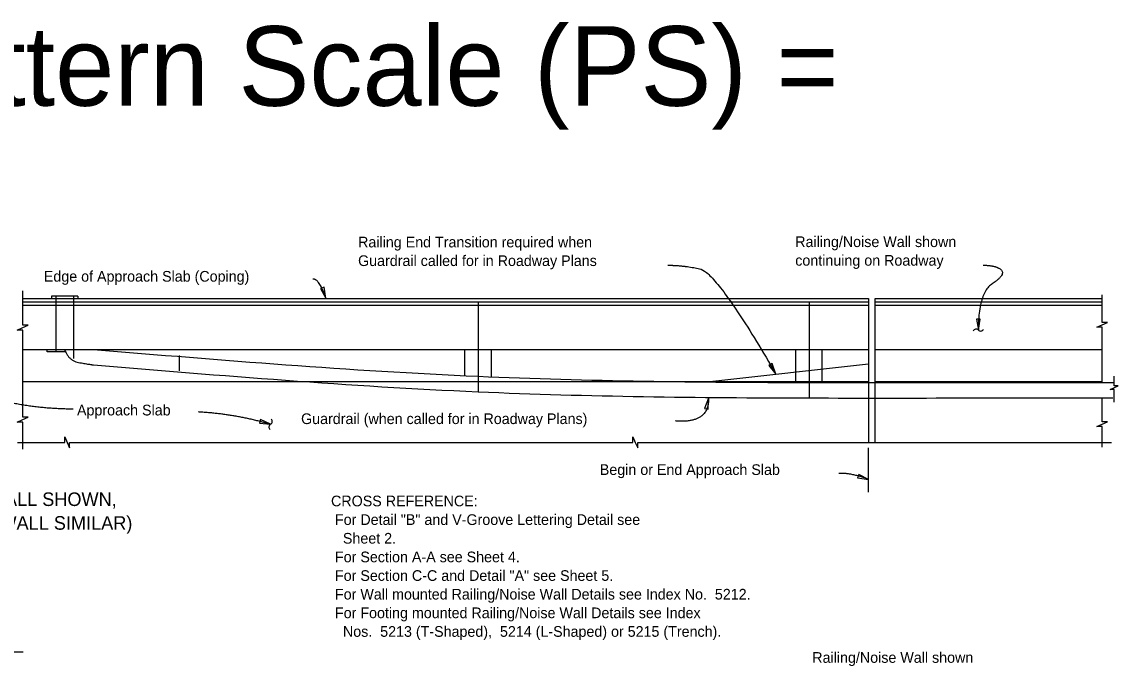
# Model space of a CAD drawing. Extents: x 120631.6 to 120706.2, y 120663.5 to 120716.4.
# Drawn here: x 120654.13 to 120674.84, y 120703.76 to 120715.93 of the extents above; entities that cross this region are included whole.
import ezdxf

# ---------------------------------------------------------------- set-up
doc = ezdxf.new("R2010")
doc.units = 0
for name, color, linetype in [('CL_Minor', 7, 'Continuous'), ('Dimension', 7, 'Continuous'), ('SteelMisc_h', 7, 'Continuous'), ('TextStructures', 7, 'Continuous'), ('TrafBarrierConc', 7, 'Continuous')]:
    doc.layers.add(name, color=color, linetype=linetype)

msp = doc.modelspace()

# ---------------------------------------------------------------- linework, layer by layer
at = {"layer": 'CL_Minor'}
for p, q in [((120654.773, 120710.751), (120654.773, 120709.697)), ((120655.106, 120710.751), (120655.106, 120709.568)), ((120662.752, 120710.639), (120662.752, 120708.943)), ((120669.002, 120710.639), (120669.002, 120708.826))]:
    msp.add_line(p, q, dxfattribs=at)
at = {"layer": 'Dimension'}
msp.add_line((120670.127, 120707.045), (120670.127, 120707.886), dxfattribs=at)
for points in [[(120659.875, 120710.708), (120659.842, 120710.917), (120659.775, 120710.894)], [(120672.2, 120710.108), (120672.235, 120710.316), (120672.165, 120710.316)], [(120668.377, 120709.277), (120668.303, 120709.475), (120668.242, 120709.439)], [(120667.103, 120708.824), (120667.029, 120708.627), (120667.098, 120708.613)], [(120658.83, 120708.328), (120658.639, 120708.419), (120658.62, 120708.352)], [(120670.127, 120707.285), (120669.94, 120707.382), (120669.918, 120707.315)]]:
    msp.add_lwpolyline(points, close=True, dxfattribs=at)
for points in [[(120654.146, 120709.139), (120654.146, 120710.109), (120654.043, 120710.109), (120654.146, 120710.154), (120654.249, 120710.199), (120654.146, 120710.199), (120654.146, 120710.849)], [(120674.539, 120709.118), (120674.539, 120710.16), (120674.436, 120710.16), (120674.539, 120710.205), (120674.643, 120710.25), (120674.539, 120710.25), (120674.539, 120710.776)], [(120674.767, 120708.747), (120674.767, 120708.988), (120674.69, 120708.988), (120674.84, 120709.054), (120674.767, 120709.054), (120674.767, 120709.24)], [(120654.146, 120707.861), (120654.146, 120708.372), (120654.043, 120708.372), (120654.146, 120708.417), (120654.249, 120708.462), (120654.146, 120708.462), (120654.146, 120709.139)], [(120674.539, 120707.897), (120674.539, 120708.288), (120674.436, 120708.288), (120674.539, 120708.333), (120674.643, 120708.378), (120674.539, 120708.378), (120674.539, 120708.826)], [(120654.046, 120707.987), (120654.939, 120707.987), (120654.939, 120708.09), (120654.984, 120707.987), (120655.029, 120707.884), (120655.029, 120707.987), (120660.919, 120707.987)], [(120660.919, 120707.987), (120665.674, 120707.987), (120665.674, 120708.09), (120665.719, 120707.987), (120665.764, 120707.884), (120665.764, 120707.987), (120674.716, 120707.987)], [(120641.607, 120704.035), (120645.965, 120704.035), (120645.965, 120704.138), (120646.01, 120704.035), (120646.055, 120703.931), (120646.055, 120704.035), (120654.156, 120704.035)]]:
    msp.add_lwpolyline(points, dxfattribs=at)
for centre, start, end in [((120672.158, 120710.066), 44.1793, 155.9065), ((120672.243, 120710.149), 224.1793, 335.9065), ((120658.802, 120708.381), 298.0989, 49.8261), ((120658.858, 120708.276), 118.0989, 229.8261)]:
    msp.add_arc(centre, 0.0596, start, end, dxfattribs=at)
for points in [[(120666.332, 120711.332), (120666.62, 120711.332), (120667.258, 120711.197), (120668.377, 120709.277)], [(120672.29, 120711.332), (120672.542, 120711.332), (120672.722, 120711.152), (120672.2, 120710.81), (120672.2, 120710.108)], [(120659.875, 120710.708), (120659.753, 120711.071), (120659.63, 120711.071)], [(120653.422, 120708.863), (120654.259, 120708.622), (120655.097, 120708.622)], [(120667.103, 120708.824), (120667.116, 120708.338), (120666.476, 120708.391)], [(120658.83, 120708.328), (120658.148, 120708.524), (120657.467, 120708.561)], [(120670.127, 120707.285), (120669.829, 120707.408), (120669.562, 120707.402)]]:
    msp.add_open_spline(points, degree=2, dxfattribs=at)
at = {"layer": 'SteelMisc_h'}
for p, q in [((120655.189, 120710.751), (120654.689, 120710.751)), ((120654.689, 120710.751), (120654.689, 120710.701)), ((120655.189, 120710.751), (120655.189, 120710.701)), ((120654.606, 120709.697), (120654.606, 120709.743)), ((120654.949, 120709.697), (120654.606, 120709.697)), ((120662.502, 120709.246), (120662.502, 120709.743)), ((120663.002, 120709.224), (120663.002, 120709.743)), ((120668.752, 120709.119), (120668.752, 120709.743)), ((120669.252, 120709.118), (120669.252, 120709.743)), ((120657.106, 120709.338), (120657.106, 120709.63)), ((120671.959, 120709.118), (120674.767, 120709.118)), ((120671.959, 120708.826), (120674.742, 120708.826))]:
    msp.add_line(p, q, dxfattribs=at)
msp.add_open_spline([(120654.939, 120709.743), (120655.009, 120709.531), (120655.402, 120709.459), (120655.483, 120709.451)], degree=2, dxfattribs=at)
for points in [[(120655.483, 120709.743), (120662.752, 120709.235), (120669.002, 120709.118), (120671.959, 120709.118)], [(120655.483, 120709.451), (120662.748, 120708.943), (120668.999, 120708.826), (120671.959, 120708.826)]]:
    msp.add_spline(points, degree=3, dxfattribs=at)
at = {"layer": 'TrafBarrierConc'}
for p, q in [((120654.146, 120710.701), (120670.127, 120710.701)), ((120670.127, 120710.701), (120670.127, 120707.987)), ((120670.25, 120710.701), (120674.539, 120710.701)), ((120670.25, 120707.987), (120670.25, 120710.701)), ((120654.146, 120710.639), (120670.127, 120710.639)), ((120654.146, 120710.576), (120670.127, 120710.576)), ((120670.25, 120710.639), (120674.539, 120710.639)), ((120670.25, 120710.576), (120674.539, 120710.576)), ((120654.146, 120709.743), (120670.127, 120709.743)), ((120670.25, 120709.743), (120674.539, 120709.743)), ((120667.127, 120709.139), (120670.127, 120709.47)), ((120654.146, 120709.139), (120670.127, 120709.139)), ((120670.25, 120709.139), (120674.539, 120709.139))]:
    msp.add_line(p, q, dxfattribs=at)

# ---------------------------------------------------------------- texts
at = {"layer": 'Dimension'}
for s, height, p in [('Railing End Transition required when ', 0.2016, (120660.482, 120711.669)), ('Railing/Noise Wall shown', 0.2016, (120668.741, 120711.675)), ('Guardrail called for in Roadway Plans', 0.2016, (120660.482, 120711.317)), ('continuing on Roadway', 0.2016, (120668.741, 120711.323)), ('Begin or End Approach Slab', 0.2016, (120665.049, 120707.372)), ('PLAN (BRIDGE MOUNTED RAILING/NOISE WALL SHOWN, ', 0.256, (120646.526, 120706.786)), ('CROSS REFERENCE:', 0.2016, (120659.971, 120706.78)), ('WALL OR FOOTING MOUNTED RAILING/NOISE WALL SIMILAR)', 0.256, (120645.966, 120706.338)), (' For Detail "B" and V-Groove Lettering Detail see ', 0.2016, (120659.971, 120706.428)), ('   Sheet 2.', 0.2016, (120659.971, 120706.076)), (' For Section A-A see Sheet 4.', 0.2016, (120659.971, 120705.724)), (' For Section C-C and Detail "A" see Sheet 5.', 0.2016, (120659.971, 120705.372)), (' For Wall mounted Railing/Noise Wall Details see Index No.  5212.', 0.2016, (120659.971, 120705.02)), (' For Footing mounted Railing/Noise Wall Details see Index ', 0.2016, (120659.971, 120704.668)), ('   Nos.  5213 (T-Shaped),  5214 (L-Shaped) or 5215 (Trench).', 0.2016, (120659.971, 120704.316)), ('Railing/Noise Wall shown', 0.2016, (120669.063, 120703.825))]:
    msp.add_text(s, height=height, dxfattribs=at).set_placement(p)
at = {"layer": 'TextStructures'}
for s, height, p in [('Pattern Scale (PS) = ', 1.50273, (120651.185, 120714.343)), ('Edge of Approach Slab (Coping)', 0.2016, (120654.546, 120711.022)), ('Approach Slab', 0.2016, (120655.172, 120708.496)), ('Guardrail (when called for in Roadway Plans)', 0.2016, (120659.405, 120708.333))]:
    msp.add_text(s, height=height, dxfattribs=at).set_placement(p)

doc.saveas('drawing.dxf')
